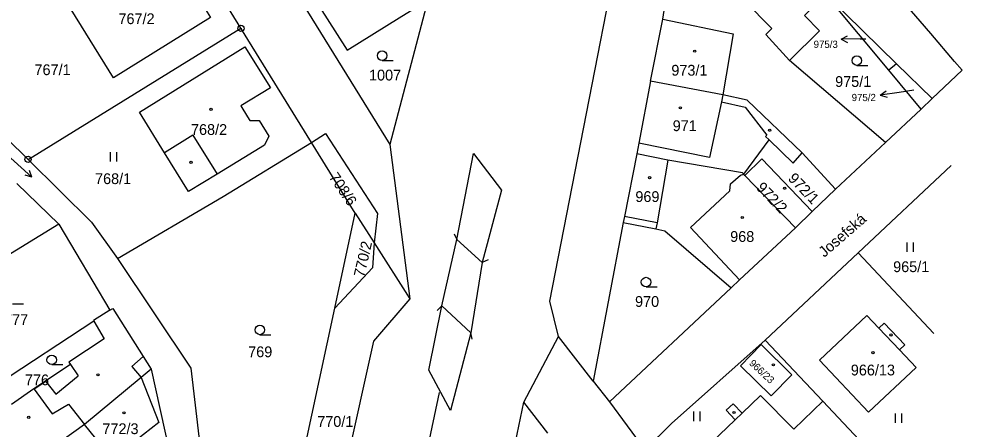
# Model space of a CAD drawing. Extents: x -776701 to -776081, y -974398 to -973771.
# Drawn here: x -776229.3 to -776080.7, y -973949 to -973884.4 of the extents above; entities that cross this region are included whole.
import ezdxf

# ---------------------------------------------------------------- set-up
doc = ezdxf.new("R2010")
doc.units = 0
for name, color, linetype in [('Hranice parcel', 7, 'Continuous'), ('Parcelní čísla', 7, 'Continuous'), ('Pop  PČ popisy', 7, 'Continuous'), ('Poz předměty', 7, 'Continuous'), ('Vnitřní kresba', 7, 'Continuous'), ('Značky bodu BP', 7, 'Continuous'), ('Značky budov', 7, 'Continuous'), ('Značky kultur', 7, 'Continuous')]:
    doc.layers.add(name, color=color, linetype=linetype)

msp = doc.modelspace()

# ---------------------------------------------------------------- linework, layer by layer
at = {"layer": 'Hranice parcel'}
for p, q in [((-776185.35, -973880.74), (-776170.9, -973904.16)), ((-776092.25, -973892.45), (-776102.18, -973880.53)), ((-776102.18, -973880.53), (-776091.04, -973891.43)), ((-776194.35, -973885.85), (-776196.99, -973881.56)), ((-776164.9, -973881.43), (-776170.9, -973904.16)), ((-776227.9, -973906.51), (-776194.35, -973885.85)), ((-776183.26, -973903.85), (-776194.35, -973885.85)), ((-776091.04, -973891.43), (-776092.25, -973892.45)), ((-776087.19, -973898.58), (-776092.25, -973892.45)), ((-776091.04, -973891.43), (-776085.43, -973896.92)), ((-776080.71, -973892.46), (-776085.43, -973896.92)), ((-776085.43, -973896.92), (-776087.19, -973898.58)), ((-776087.19, -973898.58), (-776092.78, -973903.83)), ((-776183.26, -973903.85), (-776181.01, -973902.43)), ((-776176.37, -973914.99), (-776183.26, -973903.85)), ((-776170.9, -973904.16), (-776167.74, -973928.46)), ((-776092.78, -973903.83), (-776100.68, -973911.21)), ((-776127.06, -973906.61), (-776131.99, -973905.62)), ((-776100.68, -973911.21), (-776105.9, -973905.49)), ((-776082.42, -973907.47), (-776097.07, -973921.25)), ((-776114.94, -973909.04), (-776115.12, -973908.86)), ((-776229.69, -973910.31), (-776223.06, -973916.72)), ((-776106.98, -973917.29), (-776114.94, -973909.04)), ((-776100.68, -973911.21), (-776104.32, -973914.72)), ((-776104.32, -973914.72), (-776106.98, -973917.29)), ((-776179.58, -973929.94), (-776176.37, -973914.99)), ((-776176.37, -973914.99), (-776173.38, -973919.66)), ((-776223.06, -973916.72), (-776233.23, -973922.95)), ((-776223.06, -973916.72), (-776215, -973930.29)), ((-776134.12, -973916.43), (-776138.86, -973941.44)), ((-776134.12, -973916.43), (-776128.96, -973917.47)), ((-776173.38, -973919.66), (-776167.74, -973928.46)), ((-776097.07, -973921.25), (-776111.76, -973934.97)), ((-776097.07, -973921.25), (-776085.15, -973933.96)), ((-776117.13, -973926.74), (-776136.26, -973944.7)), ((-776215, -973930.29), (-776214.56, -973930.02)), ((-776189.59, -973976.54), (-776179.58, -973929.94)), ((-776217.53, -973932.01), (-776237.1, -973944.84)), ((-776149.78, -973944.77), (-776144.3, -973934.4)), ((-776138.86, -973941.44), (-776144.3, -973934.4)), ((-776111.76, -973934.97), (-776102.68, -973944.59)), ((-776208.49, -973939.59), (-776210.07, -973940.9)), ((-776208.49, -973939.59), (-776205.5, -973953.09)), ((-776210.07, -973940.9), (-776219, -973948.3)), ((-776138.86, -973941.44), (-776136.26, -973944.7)), ((-776102.68, -973944.59), (-776107.23, -973949.03)), ((-776102.68, -973944.59), (-776091.19, -973956.75)), ((-776145.99, -973949.66), (-776149.78, -973944.77)), ((-776136.26, -973944.7), (-776130.7, -973952.3)), ((-776219, -973948.3), (-776228.72, -973955.21))]:
    msp.add_line(p, q, dxfattribs=at)
for points in [[(-776144.3, -973934.4), (-776145.69, -973928.87), (-776129.26, -973844.64)], [(-776080.71, -973892.46), (-776081.89, -973891.08), (-776085.65, -973886.69), (-776089.68, -973881.97), (-776098.69, -973871.44)], [(-776221.8, -973881.78), (-776206.58, -973872.23), (-776204.18, -973876.06), (-776201.92, -973874.65), (-776199.26, -973878.91), (-776201.52, -973880.32), (-776199.13, -973884.16), (-776214.43, -973893.65), (-776221.8, -973881.78)], [(-776183.56, -973879.96), (-776177.64, -973889.3), (-776169.41, -973884.22), (-776164.9, -973881.43)], [(-776092.78, -973903.83), (-776107.89, -973890.94), (-776103.16, -973886.26), (-776105.53, -973883.85), (-776102.18, -973880.53)], [(-776129.79, -973894.18), (-776127.86, -973884.42), (-776127.43, -973881.7)], [(-776232.47, -973884.28), (-776231.24, -973903.2), (-776227.9, -973906.51)], [(-776206.39, -973905.45), (-776210.35, -973899.05), (-776193.72, -973888.77), (-776189.72, -973895.24), (-776194.36, -973898.08), (-776193.32, -973899.78), (-776192.94, -973900.4), (-776191.5, -973900.38), (-776189.96, -973902.86), (-776190.65, -973904.27), (-776198.11, -973908.86), (-776202.61, -973911.57), (-776206.39, -973905.45)], [(-776129.79, -973894.18), (-776131.67, -973903.95), (-776131.99, -973905.62)], [(-776105.9, -973905.49), (-776114.6, -973897.2), (-776118.4, -973896.32), (-776129.79, -973894.18)], [(-776181.01, -973902.43), (-776172.82, -973915.04), (-776173.38, -973919.66)], [(-776213.8, -973922.1), (-776197.17, -973912.38), (-776183.26, -973903.85)], [(-776115.12, -973908.86), (-776111.11, -973903.44), (-776107.31, -973907.11), (-776105.9, -973905.49)], [(-776131.99, -973905.62), (-776133.9, -973915.5), (-776134.12, -973916.43)], [(-776227.9, -973906.51), (-776217.91, -973916.41), (-776213.8, -973922.1)], [(-776127.06, -973906.61), (-776128.75, -973916.49), (-776128.96, -973917.47)], [(-776115.12, -973908.86), (-776115.34, -973908.63), (-776127.06, -973906.61)], [(-776114.94, -973909.04), (-776112.25, -973906.44), (-776104.32, -973914.72)], [(-776128.96, -973917.47), (-776127.55, -973917.76), (-776117.13, -973926.74)], [(-776106.98, -973917.29), (-776115.79, -973925.51), (-776117.13, -973926.74)], [(-776173.38, -973919.66), (-776173.61, -973923.61), (-776179.58, -973929.94)], [(-776213.8, -973922.1), (-776202.27, -973939.42), (-776200.89, -973951.06), (-776189.59, -973976.54)], [(-776167.74, -973928.46), (-776173.47, -973935.17), (-776186.46, -973993.62)], [(-776215, -973930.29), (-776217.59, -973931.91), (-776217.53, -973932.01)], [(-776214.56, -973930.02), (-776212.64, -973932.99), (-776209.77, -973937.56), (-776208.49, -973939.59)], [(-776093.82, -973933.09), (-776092.98, -973932.3), (-776089.75, -973935.72), (-776090.59, -973936.52), (-776087.97, -973939.29), (-776095.44, -973946.33), (-776103.19, -973938.15), (-776095.71, -973931.09), (-776093.82, -973933.09)], [(-776217.53, -973932.01), (-776215.92, -973934.78), (-776221.49, -973938.47), (-776221.22, -973938.85)], [(-776130.7, -973952.3), (-776126.49, -973948.15), (-776111.76, -973934.97)], [(-776110.8, -973943.79), (-776115.66, -973939.02), (-776112.39, -973935.69), (-776107.53, -973940.46), (-776110.8, -973943.79)], [(-776221.22, -973938.85), (-776226.99, -973942.64), (-776230.52, -973945.14)], [(-776210.07, -973940.9), (-776207.31, -973947.95), (-776210.89, -973950.8), (-776214.54, -973953.81), (-776219, -973948.3)], [(-776107.23, -973949.03), (-776112.46, -973943.72), (-776115.35, -973946.49), (-776116.81, -973945.05), (-776117.87, -973946.03), (-776116.47, -973947.55), (-776123.77, -973954.53), (-776118.42, -973959.96)], [(-776168.94, -974014.19), (-776157.37, -973981.34), (-776149.78, -973944.77)]]:
    msp.add_lwpolyline(points, dxfattribs=at)
at = {"layer": 'Pop  PČ popisy'}
for p, q in [((-776099.76, -973887.58), (-776098.77, -973887.06)), ((-776096.76, -973887.53), (-776099.76, -973887.58)), ((-776099.76, -973887.58), (-776098.75, -973888.07)), ((-776096.76, -973887.53), (-776095.88, -973887.53)), ((-776093.6, -973896.36), (-776092.68, -973895.72)), ((-776090.63, -973895.94), (-776093.6, -973896.36)), ((-776093.6, -973896.36), (-776092.54, -973896.71)), ((-776088.33, -973895.61), (-776090.63, -973895.94))]:
    msp.add_line(p, q, dxfattribs=at)
at = {"layer": 'Poz předměty'}
msp.add_line((-776170.99, -973981), (-776163.09, -973943.22), dxfattribs=at)
at = {"layer": 'Vnitřní kresba'}
for p, q in [((-776115, -973881.5), (-776110.7, -973885.9)), ((-776127.86, -973884.42), (-776116.8, -973886.7)), ((-776110.7, -973885.9), (-776111.65, -973886.8)), ((-776116.8, -973886.7), (-776118.4, -973896.32)), ((-776111.65, -973886.8), (-776107.89, -973890.94)), ((-776118.4, -973896.32), (-776118.64, -973897.46)), ((-776118.64, -973897.46), (-776120.5, -973906.19)), ((-776118.64, -973897.46), (-776114.89, -973898.26)), ((-776114.89, -973898.26), (-776111.48, -973902.67)), ((-776201.93, -973902.69), (-776206.39, -973905.45)), ((-776201.93, -973902.69), (-776198.11, -973908.86)), ((-776111.48, -973902.67), (-776111.69, -973902.88)), ((-776111.69, -973902.88), (-776111.11, -973903.44)), ((-776120.5, -973906.19), (-776131.67, -973903.95)), ((-776160.34, -973919.15), (-776157.7, -973905.58)), ((-776157.7, -973905.58), (-776153.31, -973911.37)), ((-776115.62, -973908.99), (-776115.12, -973908.86)), ((-776117.3, -973911.45), (-776117.2, -973910.35)), ((-776117.2, -973910.35), (-776115.62, -973908.99)), ((-776153.31, -973911.37), (-776156.33, -973922.78)), ((-776123.5, -973917.25), (-776117.3, -973911.45)), ((-776128.75, -973916.49), (-776133.9, -973915.5)), ((-776115.79, -973925.51), (-776123.5, -973917.25)), ((-776162.72, -973929.6), (-776160.34, -973919.15)), ((-776160.73, -973918.23), (-776160.34, -973919.15)), ((-776160.34, -973919.15), (-776156.33, -973922.78)), ((-776155.42, -973922.36), (-776156.33, -973922.78)), ((-776156.33, -973922.78), (-776158.14, -973933.84)), ((-776164.74, -973939.7), (-776162.72, -973929.6)), ((-776163.43, -973930.31), (-776162.72, -973929.6)), ((-776162.72, -973929.6), (-776158.14, -973933.84)), ((-776158.14, -973933.84), (-776161.33, -973946.08)), ((-776157.93, -973934.82), (-776158.14, -973933.84)), ((-776093.82, -973933.09), (-776090.59, -973936.52)), ((-776209.77, -973937.56), (-776211.54, -973939.13)), ((-776221.22, -973938.85), (-776219.98, -973940.61)), ((-776211.54, -973939.13), (-776210.07, -973940.9)), ((-776161.33, -973946.08), (-776164.74, -973939.7)), ((-776225.11, -973941.52), (-776226.93, -973942.72)), ((-776225.11, -973941.52), (-776223.53, -973943.48)), ((-776223.53, -973943.48), (-776219.98, -973940.61)), ((-776226.99, -973942.64), (-776226.93, -973942.72)), ((-776226.93, -973942.72), (-776224.1, -973946.6)), ((-776224.1, -973946.6), (-776221.55, -973945.1)), ((-776221.55, -973945.1), (-776219, -973948.3)), ((-776116.47, -973947.55), (-776115.35, -973946.49))]:
    msp.add_line(p, q, dxfattribs=at)
at = {"layer": 'Značky bodu BP'}
for centre, radius in [((-776194.35, -973885.85), 0.5), ((-776194.35, -973885.85), 0.0303), ((-776227.9, -973906.51), 0.5), ((-776227.9, -973906.51), 0.0303)]:
    msp.add_circle(centre, radius, dxfattribs=at)
at = {"layer": 'Značky budov'}
for centre in [(-776122.85, -973889.45), (-776199.07, -973898.61), (-776125.11, -973898.38), (-776111.03, -973901.91), (-776202.22, -973906.96), (-776129.95, -973909.38), (-776108.67, -973911.05), (-776115.35, -973915.66), (-776091.93, -973934.17), (-776094.76, -973936.96), (-776110.45, -973938.88), (-776216.88, -973940.46), (-776227.8, -973947.17), (-776212.79, -973946.45), (-776116.65, -973946.39)]:
    msp.add_circle(centre, 0.175, dxfattribs=at)
at = {"layer": 'Značky kultur'}
for p, q in [((-776172.11, -973890.91), (-776170.36, -973890.91)), ((-776097.3, -973891.69), (-776095.55, -973891.69)), ((-776231.75, -973905.28), (-776227.29, -973909.3)), ((-776214.91, -973906.85), (-776214.91, -973905.35)), ((-776213.91, -973906.85), (-776213.91, -973905.35)), ((-776227.29, -973909.3), (-776227.68, -973908.27)), ((-776227.29, -973909.3), (-776228.35, -973909.01)), ((-776089.35, -973921.09), (-776089.35, -973919.59)), ((-776088.35, -973921.09), (-776088.35, -973919.59)), ((-776130.52, -973926.59), (-776128.77, -973926.59)), ((-776230.37, -973929.26), (-776228.62, -973929.26)), ((-776191.37, -973934.13), (-776189.62, -973934.13)), ((-776224.17, -973938.85), (-776222.42, -973938.85)), ((-776123, -973947.76), (-776123, -973946.26)), ((-776122, -973947.76), (-776122, -973946.26)), ((-776091.21, -973948.03), (-776091.21, -973946.53)), ((-776090.21, -973948.03), (-776090.21, -973946.53))]:
    msp.add_line(p, q, dxfattribs=at)
for centre in [(-776172.11, -973890.16), (-776097.3, -973890.94), (-776130.52, -973925.84), (-776191.37, -973933.38), (-776224.17, -973938.1)]:
    msp.add_circle(centre, 0.75, dxfattribs=at)

# ---------------------------------------------------------------- texts
at = {"layer": 'Parcelní čísla'}
for s, height, p in [('767/2', 1.7, (-776213.65, -973885.19)), ('975/3', 1.139, (-776104.11, -973888.94)), ('767/1', 1.7, (-776226.88, -973893.23)), ('1007', 1.7, (-776174.17, -973894.07)), ('973/1', 1.7, (-776126.53, -973893.31)), ('975/1', 1.7, (-776100.72, -973895.09)), ('975/2', 1.139, (-776098.12, -973897.32)), ('768/2', 1.7, (-776202.22, -973902.65)), ('971', 1.7, (-776126.32, -973902.05)), ('768/1', 1.7, (-776217.34, -973910.4)), ('969', 1.7, (-776132.2, -973913.22)), ('968', 1.7, (-776117.26, -973919.51)), ('965/1', 1.7, (-776091.58, -973924.27)), ('970', 1.7, (-776132.25, -973929.75)), ('777', 1.7, (-776231.68, -973932.62)), ('769', 1.7, (-776193.21, -973937.68)), ('966/13', 1.7, (-776098.25, -973940.55)), ('776', 1.7, (-776228.39, -973942.1)), ('770/1', 1.7, (-776182.33, -973948.66)), ('772/3', 1.7, (-776216.18, -973949.8))]:
    msp.add_text(s, height=height, dxfattribs=at).set_placement(p)
for s, height, rotation, p in [('708/6', 1.7, 304, (-776180.56, -973909.3)), ('972/1', 1.7, 314, (-776108.26, -973909.62)), ('972/2', 1.7, 314, (-776113.27, -973911.07)), ('770/2', 1.7, 77, (-776174.95, -973925.17)), ('966/23', 1.139, 317, (-776114.36, -973938.76))]:
    msp.add_text(s, height=height, rotation=rotation, dxfattribs=at).set_placement(p)
at = {"layer": 'Pop  PČ popisy'}
msp.add_text('Josefská', height=1.7, rotation=41, dxfattribs=at).set_placement((-776102.43, -973922.03))

doc.saveas('drawing.dxf')
